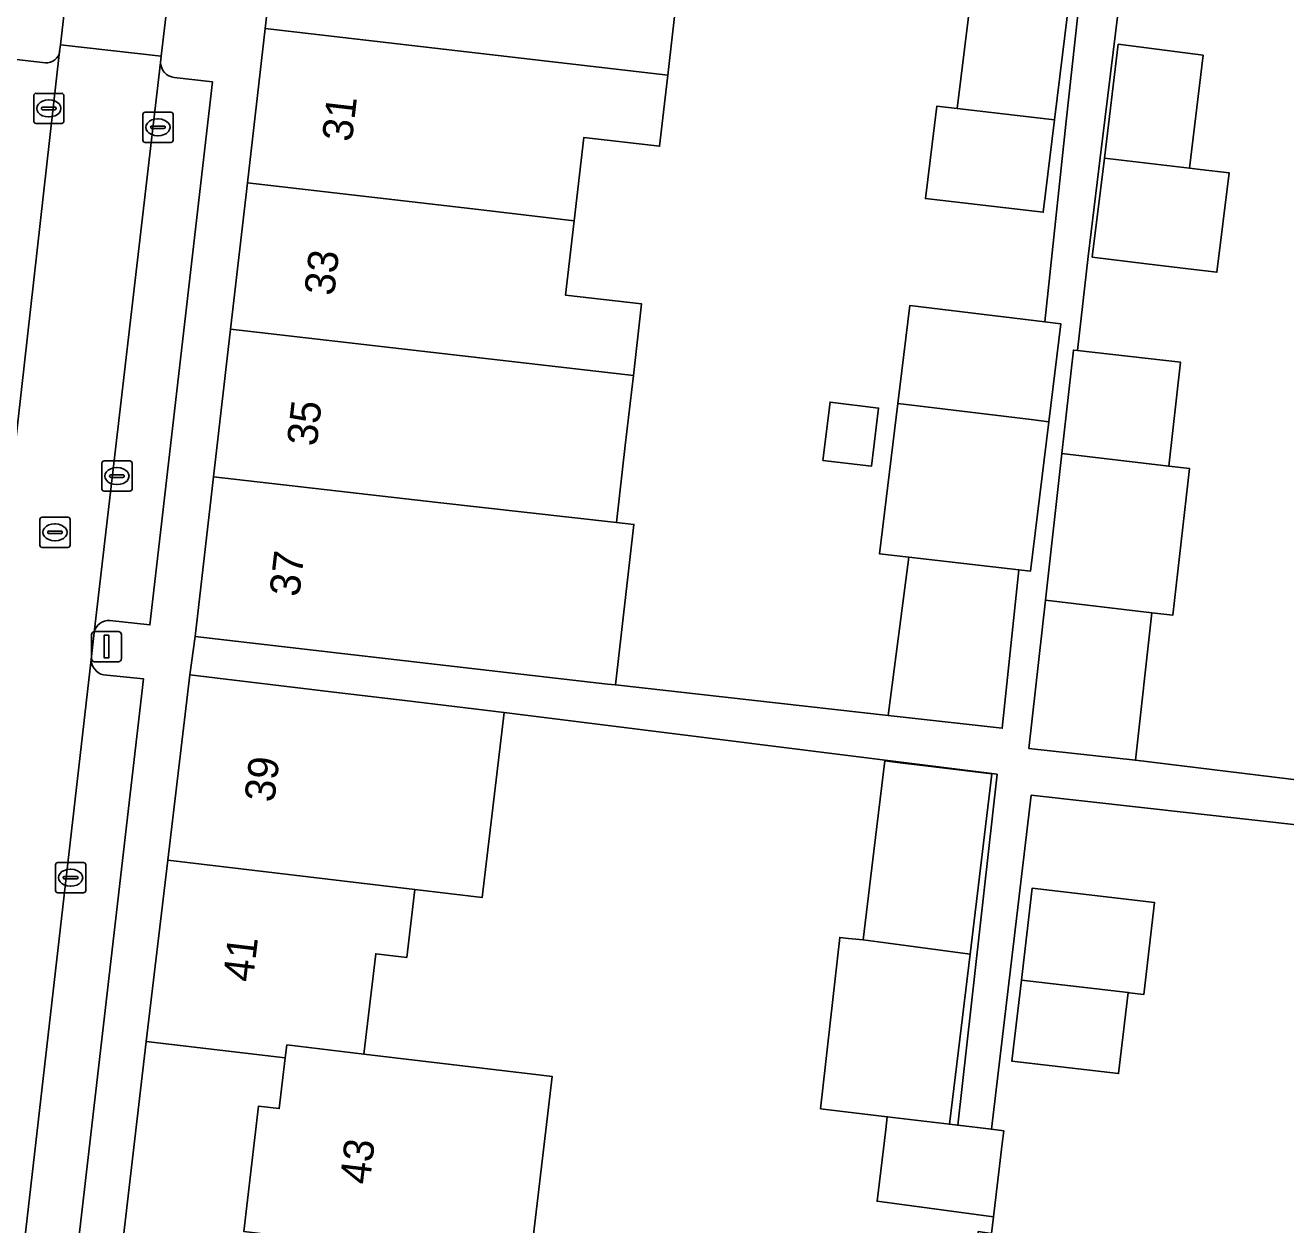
# Model space of a CAD drawing. Extents: x 161692 to 162379, y 380760 to 381678.
# Drawn here: x 161949.35 to 161991.17, y 381028.56 to 381068.36 of the extents above; entities that cross this region are included whole.
import ezdxf

# ---------------------------------------------------------------- set-up
doc = ezdxf.new("R2010")
doc.units = 0
for name, color, linetype in [('IMGEO_Erf', 7, 'Continuous'), ('IMGEO_Kolk', 7, 'Continuous'), ('IMGEO_Lichtmast', 7, 'Continuous'), ('IMGEO_Pand', 7, 'Continuous'), ('IMGEO_Pand_nummerreeks', 7, 'Continuous'), ('IMGEO_Parkeervlak_open', 7, 'Continuous'), ('IMGEO_Rijbaan_lokaal_open', 7, 'Continuous'), ('IMGEO_Rioolput', 7, 'Continuous'), ('IMGEO_Voetpad_open', 7, 'Continuous')]:
    doc.layers.add(name, color=color, linetype=linetype)

msp = doc.modelspace()

# ---------------------------------------------------------------- linework, layer by layer
at = {"layer": 'IMGEO_Erf'}
for points in [[(161991.792, 381092.98), (161988.59, 381093.391), (161987.931, 381088.252), (161987.811, 381086.967), (161987.384, 381083.453), (161986.779, 381078.489), (161986.2, 381073.729), (161985.601, 381068.808), (161985.01, 381063.958), (161984.611, 381060.68), (161984.26, 381057.563), (161987.669, 381057.182), (161987.283, 381053.735), (161987.968, 381053.655), (161987.423, 381048.79), (161986.722, 381048.869), (161986.174, 381043.974), (161991.781, 381043.296)], [(161970.922, 381068.935), (161970.664, 381066.7), (161970.392, 381064.343), (161967.88, 381064.634), (161967.56, 381061.873), (161967.274, 381059.401), (161969.797, 381059.11), (161969.522, 381056.732), (161969.253, 381054.412), (161968.959, 381051.865), (161969.539, 381051.797), (161968.925, 381046.472), (161977.976, 381045.458), (161978.658, 381050.714), (161977.683, 381050.827), (161978.295, 381055.807), (161978.694, 381059.064), (161983.174, 381058.514), (161983.874, 381065.173), (161986.04, 381084.838)], [(161981.406, 381028.279), (161981.47, 381028.823), (161977.604, 381029.346), (161977.894, 381031.726), (161977.945, 381032.147), (161975.732, 381032.414), (161976.369, 381038.095), (161976.654, 381038.057), (161977.146, 381038.013), (161977.503, 381040.959), (161977.866, 381043.954), (161978.377, 381043.892), (161979.211, 381043.791), (161981.411, 381043.525), (161980.69, 381037.545), (161980.008, 381031.898), (161980.281, 381031.865), (161981.587, 381043.512), (161965.235, 381045.562), (161964.504, 381039.417), (161962.273, 381039.683), (161962.006, 381037.436), (161960.978, 381037.558), (161960.581, 381034.226), (161966.378, 381033.537), (161966.833, 381033.483), (161966.085, 381027.214)], [(161956.595, 381028.345), (161957.089, 381032.5), (161957.775, 381032.418), (161957.975, 381034.1), (161953.362, 381034.648), (161949.809, 381004.154)]]:
    msp.add_lwpolyline(points, dxfattribs=at)
for points in [[(161980.873, 381070.529), (161980.596, 381070.56), (161981.22, 381075.647), (161981.816, 381080.502), (161982.4, 381085.259), (161985.906, 381084.854), (161985.322, 381080.096), (161984.728, 381075.257), (161984.104, 381070.174), (161983.496, 381065.217), (161983.12, 381062.154), (161979.212, 381062.605), (161979.588, 381065.668), (161980.267, 381065.59)], [(161987.966, 381063.615), (161988.328, 381063.573), (161989.283, 381063.462), (161988.882, 381060.16), (161987.927, 381060.276), (161986.549, 381060.444), (161984.747, 381060.663), (161985.146, 381063.942), (161985.608, 381067.728), (161988.422, 381067.361)], [(161977.656, 381055.657), (161977.42, 381053.725), (161975.81, 381053.922), (161976.047, 381055.854)], [(161993.148, 381029.374), (161992.669, 381029.43), (161993.361, 381035.406), (161993.645, 381037.854), (161994.123, 381037.799), (161994.586, 381037.745), (161996.736, 381037.497), (161997.165, 381041.197), (161982.721, 381042.814), (161981.398, 381031.731), (161981.809, 381031.681), (161981.76, 381031.265), (161981.692, 381030.702), (161981.47, 381028.823), (161981.406, 381028.279), (161980.964, 381028.339), (161978.51, 381007.398), (161989.335, 381006.129), (161990.006, 381011.923), (161991.809, 381011.714), (161992.484, 381017.54), (161991.786, 381017.621), (161992.461, 381023.448)], [(161982.081, 381033.988), (161982.397, 381036.676), (161982.756, 381039.732), (161986.815, 381039.254), (161986.456, 381036.205), (161985.966, 381036.262), (161985.934, 381036.266), (161985.617, 381033.578)]]:
    msp.add_lwpolyline(points, close=True, dxfattribs=at)
at = {"layer": 'IMGEO_Kolk'}
for p, q in [((161949.63, 381065.171), (161949.63, 381066.023)), ((161949.705, 381066.097), (161950.557, 381066.097)), ((161950.118, 381065.877), (161950.143, 381065.877)), ((161950.631, 381066.023), (161950.631, 381065.171)), ((161949.889, 381065.591), (161949.889, 381065.603)), ((161950.327, 381065.554), (161949.929, 381065.554)), ((161949.932, 381065.64), (161950.33, 381065.64)), ((161950.141, 381065.317), (161950.116, 381065.317)), ((161950.373, 381065.603), (161950.373, 381065.591)), ((161953.25, 381064.544), (161953.25, 381065.396)), ((161953.325, 381065.47), (161954.177, 381065.47)), ((161954.251, 381065.396), (161954.251, 381064.544)), ((161950.557, 381065.097), (161949.705, 381065.097)), ((161953.509, 381064.964), (161953.509, 381064.976)), ((161953.947, 381064.927), (161953.549, 381064.927)), ((161953.552, 381065.013), (161953.95, 381065.013)), ((161953.738, 381065.25), (161953.763, 381065.25)), ((161953.993, 381064.976), (161953.993, 381064.964)), ((161954.177, 381064.47), (161953.325, 381064.47)), ((161953.761, 381064.69), (161953.736, 381064.69)), ((161951.889, 381052.975), (161951.889, 381053.827)), ((161951.964, 381053.901), (161952.816, 381053.901)), ((161952.377, 381053.681), (161952.402, 381053.681)), ((161952.89, 381053.827), (161952.89, 381052.975)), ((161952.148, 381053.395), (161952.148, 381053.407)), ((161952.586, 381053.358), (161952.188, 381053.358)), ((161952.191, 381053.444), (161952.589, 381053.444)), ((161952.632, 381053.407), (161952.632, 381053.395)), ((161952.816, 381052.901), (161951.964, 381052.901)), ((161952.4, 381053.121), (161952.375, 381053.121)), ((161950.352, 381039.653), (161950.352, 381040.505)), ((161950.427, 381040.579), (161951.279, 381040.579)), ((161950.84, 381040.359), (161950.865, 381040.359)), ((161951.353, 381040.505), (161951.353, 381039.653)), ((161950.611, 381040.073), (161950.611, 381040.085)), ((161951.049, 381040.036), (161950.651, 381040.036)), ((161950.654, 381040.122), (161951.052, 381040.122)), ((161950.863, 381039.799), (161950.838, 381039.799)), ((161951.095, 381040.085), (161951.095, 381040.073)), ((161951.279, 381039.579), (161950.427, 381039.579))]:
    msp.add_line(p, q, dxfattribs=at)
for points in [[(161949.63, 381065.171), (161949.63, 381066.023)], [(161949.705, 381066.097), (161950.557, 381066.097)], [(161950.631, 381066.023), (161950.631, 381065.171)], [(161953.25, 381064.544), (161953.25, 381065.396)], [(161953.325, 381065.47), (161954.177, 381065.47)], [(161954.251, 381065.396), (161954.251, 381064.544)], [(161950.557, 381065.097), (161949.705, 381065.097)], [(161954.177, 381064.47), (161953.325, 381064.47)], [(161951.889, 381052.975), (161951.889, 381053.827)], [(161951.964, 381053.901), (161952.816, 381053.901)], [(161952.89, 381053.827), (161952.89, 381052.975)], [(161952.816, 381052.901), (161951.964, 381052.901)], [(161950.352, 381039.653), (161950.352, 381040.505)], [(161950.427, 381040.579), (161951.279, 381040.579)], [(161951.353, 381040.505), (161951.353, 381039.653)], [(161951.279, 381039.579), (161950.427, 381039.579)]]:
    msp.add_lwpolyline(points, dxfattribs=at)
for centre, radius, start, end in [((161949.707, 381066.021), 0.0765, 91.552, 178.448), ((161949.707, 381066.021), 0.0765, 91.552, 178.448), ((161950.555, 381066.021), 0.0765, 1.552, 88.448), ((161950.555, 381066.021), 0.0765, 1.552, 88.448), ((161949.929, 381065.6), 0.0403, 85.8775, 175.7526), ((161949.926, 381065.59), 0.0366, 178.938, 274.7102), ((161950.33, 381065.597), 0.043, 264.8664, 352.4533), ((161950.334, 381065.602), 0.0386, 1.7309, 96.639), ((161953.327, 381065.394), 0.0765, 91.552, 178.448), ((161953.327, 381065.394), 0.0765, 91.552, 178.448), ((161954.175, 381065.394), 0.0765, 1.552, 88.448), ((161954.175, 381065.394), 0.0765, 1.552, 88.448), ((161949.707, 381065.173), 0.0765, 181.552, 268.448), ((161949.707, 381065.173), 0.0765, 181.552, 268.448), ((161950.555, 381065.173), 0.0765, 271.552, 358.448), ((161950.555, 381065.173), 0.0765, 271.552, 358.448), ((161953.549, 381064.973), 0.0403, 85.8775, 175.7526), ((161953.546, 381064.963), 0.0366, 178.938, 274.7102), ((161953.95, 381064.97), 0.043, 264.8664, 352.4533), ((161953.954, 381064.975), 0.0386, 1.7309, 96.639), ((161953.327, 381064.546), 0.0765, 181.552, 268.448), ((161953.327, 381064.546), 0.0765, 181.552, 268.448), ((161954.175, 381064.546), 0.0765, 271.552, 358.448), ((161954.175, 381064.546), 0.0765, 271.552, 358.448), ((161951.966, 381053.825), 0.0765, 91.552, 178.448), ((161951.966, 381053.825), 0.0765, 91.552, 178.448), ((161952.814, 381053.825), 0.0765, 1.552, 88.448), ((161952.814, 381053.825), 0.0765, 1.552, 88.448), ((161952.188, 381053.404), 0.0403, 85.8775, 175.7526), ((161952.185, 381053.394), 0.0366, 178.938, 274.7102), ((161952.589, 381053.401), 0.043, 264.8664, 352.4533), ((161952.593, 381053.406), 0.0386, 1.7309, 96.639), ((161951.966, 381052.977), 0.0765, 181.552, 268.448), ((161951.966, 381052.977), 0.0765, 181.552, 268.448), ((161952.814, 381052.977), 0.0765, 271.552, 358.448), ((161952.814, 381052.977), 0.0765, 271.552, 358.448), ((161950.429, 381040.503), 0.0765, 91.552, 178.448), ((161950.429, 381040.503), 0.0765, 91.552, 178.448), ((161951.277, 381040.503), 0.0765, 1.552, 88.448), ((161951.277, 381040.503), 0.0765, 1.552, 88.448), ((161950.651, 381040.082), 0.0403, 85.8775, 175.7526), ((161950.648, 381040.072), 0.0366, 178.938, 274.7102), ((161951.052, 381040.079), 0.043, 264.8664, 352.4533), ((161951.056, 381040.084), 0.0386, 1.7309, 96.639), ((161950.429, 381039.655), 0.0765, 181.552, 268.448), ((161950.429, 381039.655), 0.0765, 181.552, 268.448), ((161951.277, 381039.655), 0.0765, 271.552, 358.448), ((161951.277, 381039.655), 0.0765, 271.552, 358.448)]:
    msp.add_arc(centre, radius, start, end, dxfattribs=at)
for centre, major_axis, ratio, start_param, end_param in [((161950.117, 381065.597), (-0.387, 0.002), 0.722429, 4.712389, 7.853982), ((161950.142, 381065.597), (-0.39, 0.002), 0.717154, 1.570796, 4.712389), ((161953.737, 381064.97), (-0.387, 0.002), 0.722429, 4.712389, 7.853982), ((161953.762, 381064.97), (-0.39, 0.002), 0.717154, 1.570796, 4.712389), ((161952.376, 381053.401), (-0.387, 0.002), 0.722429, 4.712389, 7.853982), ((161952.401, 381053.401), (-0.39, 0.002), 0.717154, 1.570796, 4.712389), ((161950.839, 381040.079), (-0.387, 0.002), 0.722429, 4.712389, 7.853982), ((161950.864, 381040.079), (-0.39, 0.002), 0.717154, 1.570796, 4.712389)]:
    msp.add_ellipse(centre, major_axis=major_axis, ratio=ratio, start_param=start_param, end_param=end_param, dxfattribs=at)
at = {"layer": 'IMGEO_Lichtmast'}
for p, q in [((161951.55, 381047.344), (161951.55, 381048.144)), ((161951.55, 381048.144), (161951.55, 381047.344)), ((161951.65, 381048.244), (161952.44, 381048.244)), ((161952.44, 381048.244), (161951.65, 381048.244)), ((161952.54, 381048.144), (161952.54, 381047.344)), ((161952.54, 381047.344), (161952.54, 381048.144)), ((161952.44, 381047.244), (161951.65, 381047.244)), ((161951.65, 381047.244), (161952.44, 381047.244))]:
    msp.add_line(p, q, dxfattribs=at)
msp.add_lwpolyline([(161951.97, 381048.119), (161952.12, 381048.119), (161952.12, 381047.369), (161951.97, 381047.369), (161951.97, 381048.119)], dxfattribs=at)
for centre, start, end in [((161951.65, 381048.144), 90, 180), ((161951.65, 381048.144), 90, 180), ((161952.44, 381048.144), 0, 90), ((161952.44, 381048.144), 360, 90), ((161951.65, 381047.344), 180, 270), ((161951.65, 381047.344), 180, 270), ((161952.44, 381047.344), 270, 0), ((161952.44, 381047.344), 270, 0)]:
    msp.add_arc(centre, 0.1, start, end, dxfattribs=at)
at = {"layer": 'IMGEO_Pand'}
for points in [[(161968.432, 381071.991), (161965.381, 381072.343), (161957.882, 381073.21), (161957.31, 381068.245), (161970.664, 381066.7), (161970.922, 381068.935), (161968.116, 381069.26)], [(161984.104, 381070.174), (161980.873, 381070.529), (161980.267, 381065.59), (161983.496, 381065.217)], [(161970.664, 381066.7), (161957.31, 381068.245), (161956.721, 381063.128), (161964.197, 381062.262), (161967.56, 381061.873), (161967.88, 381064.634), (161970.392, 381064.343)], [(161985.146, 381063.942), (161987.966, 381063.615), (161988.422, 381067.361), (161985.608, 381067.728)], [(161983.496, 381065.217), (161980.267, 381065.59), (161979.588, 381065.668), (161979.212, 381062.605), (161983.12, 381062.154)], [(161987.966, 381063.615), (161985.146, 381063.942), (161984.747, 381060.663), (161986.549, 381060.444), (161987.927, 381060.276), (161988.882, 381060.16), (161989.283, 381063.462), (161988.328, 381063.573)], [(161969.522, 381056.732), (161969.797, 381059.11), (161967.274, 381059.401), (161967.56, 381061.873), (161964.197, 381062.262), (161956.721, 381063.128), (161956.162, 381058.279)], [(161983.707, 381058.449), (161983.174, 381058.514), (161978.694, 381059.064), (161978.295, 381055.807), (161978.949, 381055.728), (161982.719, 381055.273), (161983.309, 381055.202)], [(161956.162, 381058.279), (161955.598, 381053.379), (161963.032, 381052.52), (161968.959, 381051.865), (161969.253, 381054.412), (161969.522, 381056.732)], [(161987.669, 381057.182), (161984.26, 381057.563), (161984.119, 381057.579), (161983.735, 381054.146), (161987.283, 381053.735)], [(161975.81, 381053.922), (161977.42, 381053.725), (161977.656, 381055.657), (161976.047, 381055.854)], [(161983.309, 381055.202), (161982.719, 381055.273), (161978.949, 381055.728), (161978.295, 381055.807), (161977.683, 381050.827), (161978.658, 381050.714), (161982.31, 381050.292), (161982.7, 381050.247)], [(161986.722, 381048.869), (161987.423, 381048.79), (161987.968, 381053.655), (161987.283, 381053.735), (161983.735, 381054.146), (161983.191, 381049.281)], [(161968.959, 381051.865), (161963.032, 381052.52), (161955.598, 381053.379), (161954.987, 381048.075), (161959.954, 381047.501), (161968.663, 381046.494), (161968.925, 381046.472), (161969.539, 381051.797)], [(161982.31, 381050.292), (161978.658, 381050.714), (161977.976, 381045.458), (161981.757, 381045.035)], [(161986.722, 381048.869), (161983.191, 381049.281), (161982.641, 381044.369), (161986.174, 381043.974)], [(161954.078, 381040.659), (161962.273, 381039.683), (161964.504, 381039.417), (161965.235, 381045.562), (161961.935, 381045.955), (161959.774, 381046.212), (161954.809, 381046.803)], [(161977.503, 381040.959), (161977.146, 381038.013), (161977.976, 381037.903), (161980.69, 381037.545), (161981.411, 381043.525), (161979.211, 381043.791), (161978.377, 381043.892), (161977.866, 381043.954)], [(161954.078, 381040.659), (161953.362, 381034.648), (161957.975, 381034.1), (161958.026, 381034.53), (161960.581, 381034.226), (161960.978, 381037.558), (161962.006, 381037.436), (161962.273, 381039.683)], [(161986.815, 381039.254), (161982.756, 381039.732), (161982.397, 381036.676), (161985.934, 381036.266), (161985.966, 381036.262), (161986.456, 381036.205)], [(161980.69, 381037.545), (161977.976, 381037.903), (161977.146, 381038.013), (161976.654, 381038.057), (161976.369, 381038.095), (161975.732, 381032.414), (161977.945, 381032.147), (161980.008, 381031.898)], [(161985.934, 381036.266), (161982.397, 381036.676), (161982.081, 381033.988), (161985.617, 381033.578)], [(161960.581, 381034.226), (161958.026, 381034.53), (161957.975, 381034.1), (161957.775, 381032.418), (161957.089, 381032.5), (161956.595, 381028.345), (161962.908, 381027.593), (161963.846, 381027.481), (161966.085, 381027.214), (161966.833, 381033.483), (161966.378, 381033.537)], [(161981.692, 381030.702), (161981.76, 381031.265), (161981.809, 381031.681), (161981.398, 381031.731), (161980.281, 381031.865), (161980.008, 381031.898), (161977.945, 381032.147), (161977.894, 381031.726), (161977.604, 381029.346), (161981.47, 381028.823)]]:
    msp.add_lwpolyline(points, close=True, dxfattribs=at)
at = {"layer": 'IMGEO_Parkeervlak_open'}
for points in [[(161948.346, 381048.6), (161950.49, 381067.484)], [(161950.017, 381067.113), (161948.676, 381067.266), (161946.607, 381049.227), (161947.955, 381049.089)], [(161953.839, 381067.124), (161951.635, 381048.212)], [(161952.154, 381048.613), (161953.485, 381048.466), (161955.561, 381066.474), (161954.291, 381066.622)], [(161951.537, 381047.312), (161948.215, 381018.454)], [(161949.716, 381016.912), (161950.997, 381026.968), (161953.271, 381046.679), (161951.94, 381046.805)]]:
    msp.add_lwpolyline(points, dxfattribs=at)
for centre, radius, start, end in [((161950.059, 381067.547), 0.436, 264.4712, 351.7469), ((161954.346, 381067.126), 0.507, 180.2259, 263.7738), ((161952.127, 381048.112), 0.502, 86.9051, 168.4771), ((161952.073, 381047.324), 0.536, 181.2952, 255.6652)]:
    msp.add_arc(centre, radius, start, end, dxfattribs=at)
at = {"layer": 'IMGEO_Rijbaan_lokaal_open'}
msp.add_lwpolyline([(161953.854, 381067.335), (161954.427, 381072.168), (161951.073, 381072.558), (161950.519, 381067.711)], close=True, dxfattribs=at)
msp.add_lwpolyline([(161948.215, 381018.454), (161951.537, 381047.312), (161951.635, 381048.212), (161953.839, 381067.124), (161953.854, 381067.335), (161950.519, 381067.711), (161950.49, 381067.484), (161948.346, 381048.6), (161948.302, 381048.297), (161947.774, 381043.773), (161944.762, 381017.945)], dxfattribs=at)
at = {"layer": 'IMGEO_Rioolput'}
for p, q in [((161949.834, 381051.109), (161949.834, 381051.961)), ((161949.909, 381052.035), (161950.761, 381052.035)), ((161950.835, 381051.961), (161950.835, 381051.109)), ((161950.093, 381051.529), (161950.093, 381051.541)), ((161950.531, 381051.492), (161950.133, 381051.492)), ((161950.136, 381051.578), (161950.534, 381051.578)), ((161950.322, 381051.815), (161950.347, 381051.815)), ((161950.577, 381051.541), (161950.577, 381051.529)), ((161950.345, 381051.255), (161950.32, 381051.255)), ((161950.761, 381051.035), (161949.909, 381051.035))]:
    msp.add_line(p, q, dxfattribs=at)
for points in [[(161949.834, 381051.109), (161949.834, 381051.961)], [(161949.909, 381052.035), (161950.761, 381052.035)], [(161950.835, 381051.961), (161950.835, 381051.109)], [(161950.761, 381051.035), (161949.909, 381051.035)]]:
    msp.add_lwpolyline(points, dxfattribs=at)
for centre, radius, start, end in [((161949.911, 381051.959), 0.0765, 91.552, 178.448), ((161949.911, 381051.959), 0.0765, 91.552, 178.448), ((161950.759, 381051.959), 0.0765, 1.552, 88.448), ((161950.759, 381051.959), 0.0765, 1.552, 88.448), ((161950.133, 381051.538), 0.0403, 85.8775, 175.7526), ((161950.13, 381051.528), 0.0366, 178.938, 274.7102), ((161950.534, 381051.535), 0.043, 264.8664, 352.4533), ((161950.538, 381051.54), 0.0386, 1.7309, 96.639), ((161949.911, 381051.111), 0.0765, 181.552, 268.448), ((161949.911, 381051.111), 0.0765, 181.552, 268.448), ((161950.759, 381051.111), 0.0765, 271.552, 358.448), ((161950.759, 381051.111), 0.0765, 271.552, 358.448)]:
    msp.add_arc(centre, radius, start, end, dxfattribs=at)
for centre, major_axis, ratio, start_param, end_param in [((161950.321, 381051.535), (-0.387, 0.002), 0.722429, 4.712389, 7.853982), ((161950.346, 381051.535), (-0.39, 0.002), 0.717154, 1.570796, 4.712389)]:
    msp.add_ellipse(centre, major_axis=major_axis, ratio=ratio, start_param=start_param, end_param=end_param, dxfattribs=at)
at = {"layer": 'IMGEO_Voetpad_open'}
for points in [[(161948.338, 380991.533), (161949.325, 381000), (161949.809, 381004.154), (161953.362, 381034.648), (161954.078, 381040.659), (161954.809, 381046.803), (161954.987, 381048.075), (161955.598, 381053.379), (161956.162, 381058.279), (161956.721, 381063.128), (161957.31, 381068.245), (161957.882, 381073.21), (161958.454, 381078.175), (161958.467, 381078.174), (161959.04, 381083.136), (161959.591, 381087.897), (161960.183, 381093.023), (161960.165, 381093.025), (161960.739, 381098.013), (161960.948, 381099.82), (161961.53, 381104.876), (161962.114, 381109.945), (161962.172, 381109.938), (161962.747, 381114.909)], [(161991.781, 381043.296), (161986.174, 381043.974), (161982.641, 381044.369), (161983.191, 381049.281), (161983.735, 381054.146), (161984.119, 381057.579), (161984.26, 381057.563), (161984.611, 381060.68), (161985.01, 381063.958), (161985.601, 381068.808), (161986.2, 381073.729), (161986.779, 381078.489), (161987.384, 381083.453), (161987.811, 381086.967), (161987.931, 381088.252), (161988.59, 381093.391), (161991.792, 381092.98)], [(161986.04, 381084.838), (161983.874, 381065.173), (161983.174, 381058.514), (161983.707, 381058.449), (161983.309, 381055.202), (161982.7, 381050.247), (161982.31, 381050.292), (161981.757, 381045.035), (161977.976, 381045.458), (161968.925, 381046.472), (161968.663, 381046.494), (161959.954, 381047.501), (161954.987, 381048.075), (161954.809, 381046.803), (161959.774, 381046.212), (161961.935, 381045.955), (161965.235, 381045.562), (161981.587, 381043.512), (161980.281, 381031.865), (161981.398, 381031.731), (161982.721, 381042.814), (161997.165, 381041.197)], [(161950.49, 381067.484), (161950.519, 381067.711), (161951.073, 381072.558)], [(161954.427, 381072.168), (161953.854, 381067.335), (161953.839, 381067.124)], [(161947.955, 381049.089), (161946.607, 381049.227), (161948.676, 381067.266), (161950.017, 381067.113)], [(161954.291, 381066.622), (161955.561, 381066.474), (161953.485, 381048.466), (161952.154, 381048.613)], [(161951.635, 381048.212), (161951.537, 381047.312)], [(161951.94, 381046.805), (161953.271, 381046.679), (161950.997, 381026.968), (161949.716, 381016.912)]]:
    msp.add_lwpolyline(points, dxfattribs=at)
for centre, radius, start, end in [((161950.059, 381067.547), 0.436, 264.4712, 351.7469), ((161954.346, 381067.126), 0.507, 180.2259, 263.7738), ((161952.127, 381048.112), 0.502, 86.9051, 168.4771), ((161952.073, 381047.324), 0.536, 181.2952, 255.6652)]:
    msp.add_arc(centre, radius, start, end, dxfattribs=at)

# ---------------------------------------------------------------- texts
at = {"layer": 'IMGEO_Pand_nummerreeks'}
for s, rotation, p in [('31', 83.4054, (161960.183, 381064.468)), ('33', 83.4054, (161959.593, 381059.361)), ('35', 83.4054, (161959.016, 381054.367)), ('37', 83.4054, (161958.438, 381049.374)), ('39', 83.2111, (161957.607, 381042.555)), ('41', 83.2111, (161956.896, 381036.591)), ('43', 83.1591, (161960.772, 381029.875))]:
    msp.add_text(s, height=1, rotation=rotation, dxfattribs=at).set_placement(p)

doc.saveas('drawing.dxf')
